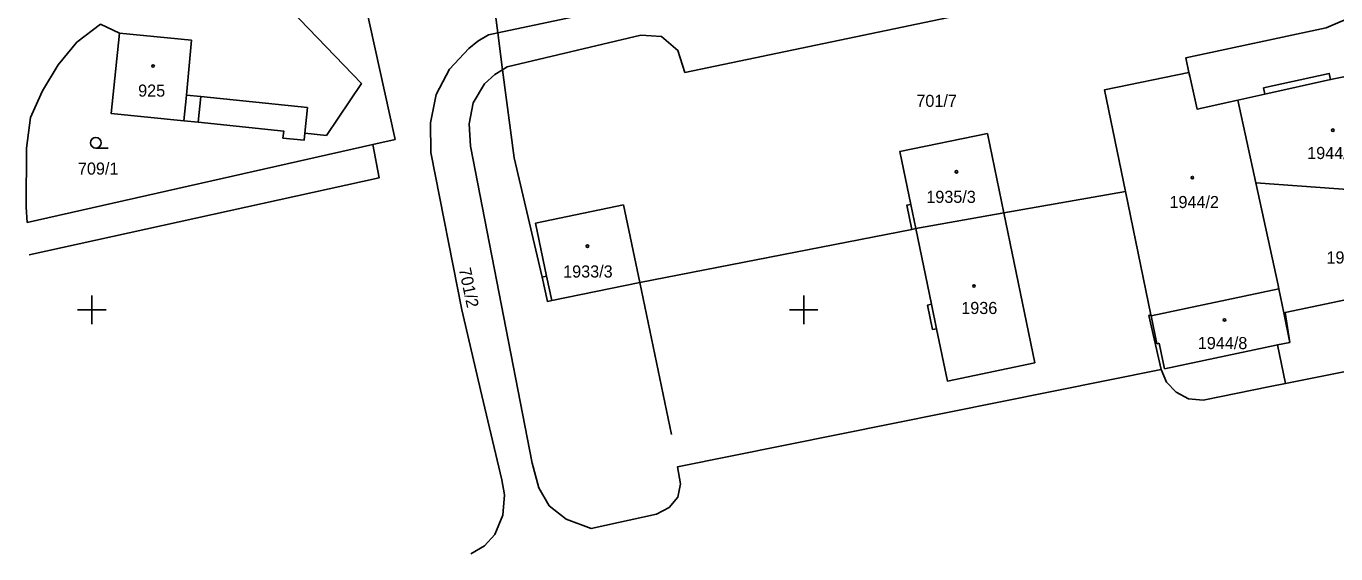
# Model space of a CAD drawing. Extents: x -779302 to -774398, y -1144902 to -1142831.
# Drawn here: x -775109.2 to -774925.2, y -1144734.3 to -1144660.1 of the extents above; entities that cross this region are included whole.
import ezdxf

# ---------------------------------------------------------------- set-up
doc = ezdxf.new("R2010")
doc.units = 0
for name, color, linetype in [('hektosit - Vrstva 5', 7, 'Continuous'), ('Hranice parcel', 7, 'Continuous'), ('Parcelní čísla', 7, 'Continuous'), ('Vnitřní kresba', 7, 'Continuous'), ('Značky budov', 7, 'Continuous'), ('Značky kultur', 7, 'Continuous')]:
    doc.layers.add(name, color=color, linetype=linetype)

msp = doc.modelspace()

# ---------------------------------------------------------------- linework, layer by layer
at = {"layer": 'hektosit - Vrstva 5'}
for p, q in [((-775100, -1144698), (-775100, -1144702)), ((-775000, -1144698), (-775000, -1144702)), ((-775102, -1144700), (-775098, -1144700)), ((-775002, -1144700), (-774998, -1144700))]:
    msp.add_line(p, q, dxfattribs=at)
at = {"layer": 'Hranice parcel'}
for p, q in [((-775042.99, -1144661.05), (-775043.55, -1144656.82)), ((-775042.33, -1144666.27), (-775042.99, -1144661.05)), ((-774939.02, -1144670.52), (-774936.49, -1144682.12)), ((-774974.18, -1144675.2), (-774971.87, -1144686.38)), ((-774954.79, -1144683.35), (-774971.87, -1144686.38)), ((-774954.79, -1144683.35), (-774951.21, -1144700.7)), ((-775025.32, -1144685.23), (-775023.03, -1144696.15)), ((-774971.87, -1144686.38), (-774984.25, -1144688.58)), ((-774967.51, -1144707.44), (-774971.87, -1144686.38)), ((-774984.81, -1144688.7), (-775023.03, -1144696.15)), ((-774984.25, -1144688.58), (-774984.81, -1144688.7)), ((-775023.03, -1144696.15), (-775035.4, -1144698.69)), ((-775018.55, -1144717.51), (-775023.03, -1144696.15)), ((-774932.31, -1144710.34), (-774911.3, -1144706.11))]:
    msp.add_line(p, q, dxfattribs=at)
for points in [[(-775042.99, -1144661.05), (-774928.91, -1144636.97)], [(-774945.87, -1144666.63), (-774946.32, -1144664.58), (-774926.62, -1144660.38), (-774922.11, -1144658.43), (-774915.55, -1144654.1), (-774913.6, -1144651.77), (-774913.25, -1144649.95), (-774914.27, -1144647.26), (-774916.78, -1144644.31), (-774920.05, -1144642.11), (-774925.78, -1144641.08), (-774958.14, -1144647.94), (-774959.58, -1144649.16), (-774960.39, -1144650.94), (-774960.12, -1144654.79), (-775016.68, -1144666.62), (-775017.69, -1144663.53), (-775019.98, -1144661.57), (-775022.9, -1144661.4), (-775041.66, -1144665.85), (-775042.33, -1144666.27)], [(-775109.1, -1144687.73), (-775060.52, -1144676.74), (-775057.4, -1144676.03), (-775062.41, -1144653.28), (-775064.48, -1144642.88)], [(-775098.79, -1144659.85), (-775096.1, -1144661.12), (-775097.27, -1144672.41), (-775087.08, -1144673.44), (-775085.07, -1144673.62), (-775073.05, -1144674.86), (-775073.16, -1144675.85), (-775070.19, -1144676.15), (-775070.09, -1144675.16), (-775067.06, -1144675.47), (-775062.14, -1144668.17), (-775078.24, -1144651.43)], [(-775109.1, -1144687.73), (-775109.23, -1144685.55), (-775109.2, -1144677.28), (-775108.63, -1144672.96), (-775108.02, -1144671.58), (-775106.96, -1144669.22), (-775104.75, -1144665.58), (-775102.1, -1144662.36), (-775098.79, -1144659.85)], [(-774939.02, -1144670.52), (-774935.21, -1144669.68), (-774935.4, -1144668.8), (-774926.17, -1144666.76), (-774925.98, -1144667.64), (-774917.05, -1144665.85), (-774917.24, -1144664.89), (-774916.52, -1144662.76), (-774914.78, -1144660.38), (-774913.04, -1144659.34), (-774911.57, -1144659.55), (-774910.63, -1144660.73), (-774906.75, -1144681.8)], [(-775042.99, -1144661.05), (-775044.27, -1144661.32), (-775045.79, -1144662.25), (-775047.06, -1144663.26), (-775049.78, -1144666.17), (-775051.65, -1144669.73), (-775052.43, -1144673.69), (-775052.39, -1144677.89), (-775048.03, -1144700), (-775045.21, -1144712.04), (-775042.43, -1144723.9), (-775042.04, -1144725.99), (-775042.27, -1144728.86), (-775043.37, -1144731.58), (-775044.82, -1144733.16), (-775046.78, -1144734.28)], [(-775029.84, -1144730.7), (-775033.39, -1144729.39), (-775035.78, -1144727.52), (-775037.23, -1144725.01), (-775038.14, -1144721.55), (-775046.83, -1144676.98), (-775047.01, -1144673.83), (-775046.44, -1144670.89), (-775044.85, -1144668.25), (-775043.37, -1144666.93), (-775042.33, -1144666.27)], [(-775036.74, -1144695.4), (-775040.69, -1144678.65), (-775042.33, -1144666.27)], [(-774954.79, -1144683.35), (-774957.74, -1144669.08), (-774945.87, -1144666.63)], [(-774945.87, -1144666.63), (-774945.75, -1144667.17), (-774944.73, -1144671.78), (-774939.02, -1144670.52)], [(-774984.81, -1144688.7), (-774985.51, -1144685.3), (-774984.96, -1144685.19), (-774986.5, -1144677.76), (-774974.18, -1144675.2)], [(-774908.46, -1144684.16), (-774913.27, -1144683.81), (-774936.49, -1144682.12)], [(-774933.24, -1144697.04), (-774933.35, -1144696.52), (-774936.49, -1144682.12)], [(-775036.74, -1144695.4), (-775036.11, -1144695.27), (-775037.66, -1144687.82), (-775025.32, -1144685.23)], [(-774984.25, -1144688.58), (-774982.05, -1144699.21), (-774982.6, -1144699.32), (-774981.89, -1144702.75), (-774981.34, -1144702.64), (-774979.81, -1144710.01), (-774967.51, -1144707.44)], [(-774932.38, -1144700.37), (-774910.73, -1144695.8), (-774912.04, -1144689.58), (-774907.24, -1144688.69)], [(-775035.4, -1144698.69), (-775036.01, -1144698.81), (-775036.74, -1144695.4)], [(-774951.21, -1144700.7), (-774951.19, -1144700.82), (-774933.24, -1144697.04)], [(-774933.24, -1144697.04), (-774932.53, -1144700.4), (-774932.38, -1144700.37)], [(-774932.38, -1144700.37), (-774931.72, -1144704.56), (-774933.45, -1144704.92), (-774932.31, -1144710.34)], [(-774951.21, -1144700.7), (-774951.49, -1144700.77), (-774949.77, -1144708.36)], [(-774949.77, -1144708.36), (-775017.71, -1144722.05), (-775017.31, -1144724.45), (-775017.66, -1144726.34), (-775018.92, -1144727.79), (-775020.67, -1144728.71), (-775029.84, -1144730.7)], [(-774932.31, -1144710.34), (-774934.47, -1144710.78), (-774943.88, -1144712.67), (-774945.92, -1144712.48), (-774947.66, -1144711.58), (-774949.05, -1144710.17), (-774949.77, -1144708.36)]]:
    msp.add_lwpolyline(points, dxfattribs=at)
at = {"layer": 'Vnitřní kresba'}
for p, q in [((-775085.99, -1144662.09), (-775096.1, -1144661.12)), ((-775086.73, -1144669.8), (-775085.99, -1144662.09)), ((-774935.21, -1144669.68), (-774925.98, -1144667.64)), ((-775086.73, -1144669.8), (-775087.08, -1144673.44)), ((-775084.7, -1144670.01), (-775086.73, -1144669.8)), ((-775085.07, -1144673.62), (-775084.7, -1144670.01)), ((-775069.71, -1144671.55), (-775084.7, -1144670.01)), ((-775070.09, -1144675.16), (-775069.71, -1144671.55)), ((-775059.63, -1144681.44), (-775060.52, -1144676.74)), ((-775108.83, -1144692.26), (-775059.63, -1144681.44)), ((-774984.96, -1144685.19), (-774984.25, -1144688.58)), ((-775036.11, -1144695.27), (-775035.4, -1144698.69)), ((-774982.05, -1144699.21), (-774981.34, -1144702.64)), ((-774932.53, -1144700.4), (-774931.72, -1144704.56)), ((-774950.39, -1144704.76), (-774951.19, -1144700.82)), ((-774950.06, -1144704.69), (-774950.39, -1144704.76)), ((-774949.33, -1144708.27), (-774950.06, -1144704.69)), ((-774933.6, -1144704.95), (-774949.33, -1144708.27)), ((-774933.45, -1144704.92), (-774933.6, -1144704.95))]:
    msp.add_line(p, q, dxfattribs=at)
at = {"layer": 'Značky budov'}
for centre in [(-775091.4, -1144665.73), (-774925.66, -1144674.75), (-774978.54, -1144680.6), (-774945.39, -1144681.42), (-775030.38, -1144691.05), (-774976.08, -1144696.65), (-774940.88, -1144701.41)]:
    msp.add_circle(centre, 0.175, dxfattribs=at)
at = {"layer": 'Značky kultur'}
msp.add_line((-775099.45, -1144677.26), (-775097.7, -1144677.26), dxfattribs=at)
msp.add_circle((-775099.45, -1144676.51), 0.75, dxfattribs=at)

# ---------------------------------------------------------------- texts
at = {"layer": 'Parcelní čísla'}
for s, p in [('925', (-775093.5, -1144670.03)), ('701/7', (-774984.17, -1144671.47)), ('1944/9', (-774929.26, -1144678.8)), ('709/1', (-775101.96, -1144680.99)), ('1935/3', (-774982.77, -1144684.96)), ('1944/2', (-774948.61, -1144685.69)), ('1944/1', (-774926.55, -1144693.48)), ('1933/3', (-775033.79, -1144695.45)), ('1936', (-774977.86, -1144700.58)), ('1944/8', (-774944.63, -1144705.51))]:
    msp.add_text(s, height=1.7, dxfattribs=at).set_placement(p)
msp.add_text('701/2', height=1.7, rotation=282, dxfattribs=at).set_placement((-775048.46, -1144694.26))

doc.saveas('drawing.dxf')
